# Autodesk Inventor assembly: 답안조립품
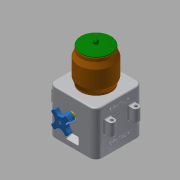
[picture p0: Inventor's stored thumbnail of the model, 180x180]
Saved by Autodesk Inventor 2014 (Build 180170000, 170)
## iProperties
Created: 2018-01
Part Number: 답안조립품
Document SubType Name: Assembly
Designer: user
Author: user
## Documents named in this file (9)
- C:\Users\user\Desktop\480108V1003\답안조립품.iam
- C:\Users\user\Desktop\480108V1003\본체.ipt
- C:\Users\user\Desktop\480108V1003\본체커버.ipt
- C:\Users\user\Desktop\480108V1003\볼트 M3x12.ipt
- C:\Users\user\Desktop\480108V1003\볼트 M4x12.ipt
- C:\Users\user\Desktop\480108V1003\용기.ipt
- C:\Users\user\Desktop\480108V1003\용기캡.ipt
- C:\Users\user\Desktop\480108V1003\핸들.ipt
- C:\Users\user\Desktop\480108V1003\핸들축.ipt
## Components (2 placed, 2 different names)
1. 핸들:1
2. 핸들축:1
